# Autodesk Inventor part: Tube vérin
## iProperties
Shininess: 20.0
Angle Display Precision: 2
Document Length Units: 11269
Document Angle Units: 11279
Document Time Units: 11290
Document Mass Units: 11283
Document Length Units Precision: 3
Document Angle Units Precision: 2
Created: 2002-09
Part Number: Tube vérin
Material: Par défaut
Document SubType Name: Modélisation
Designer: administrateur
Density: 0.0
Volumn: 0.0
Area: 0.0
PropertySet Name: Model Information
Control State: 0
Master: False
Checked Out: False
Author: administrateur
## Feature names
1. Extrusion1
2. Extrusion2
